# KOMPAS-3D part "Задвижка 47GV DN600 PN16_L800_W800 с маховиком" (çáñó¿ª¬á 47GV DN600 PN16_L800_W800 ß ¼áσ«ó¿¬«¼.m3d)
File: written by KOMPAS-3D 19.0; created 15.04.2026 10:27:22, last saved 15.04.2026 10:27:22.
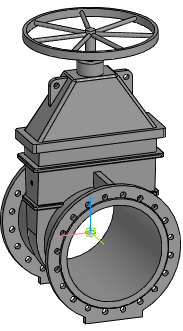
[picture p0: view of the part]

Document properties: Автор: Евгений; Полное имя файла: Z:\3.Личные\kachalov\3d для проектировщиков\2.1 Тип 47GV, 47GV.Z\Задвижка 47GV_DN40-DN600\stp_Задвижка 47GV\Задвижка 47GV DN600 PN16_L800_W800 с маховиком.m3d

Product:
- Part/product: Задвижка 47GV DN600 PN16_L800_W800 с маховиком

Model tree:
1. Операция без истории:1  (labels: Задвижка 47GV DN600 PN16_L800_W800 с маховиком)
